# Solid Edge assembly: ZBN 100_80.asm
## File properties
Title: Zylinder
Author: bmolnar
Template: iso metric assembly.asm
Last saved by: bmolnar
Revision: 20
Application: Solid Edge
Username: bmolnar
Dokumentum tartalom típus: 1
Document Number: ZBN 100/80
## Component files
Kit_2.par
Profilrohr.par
Kolbenstange.par
Kit_1.par
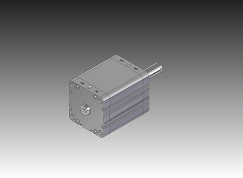
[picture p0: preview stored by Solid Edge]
